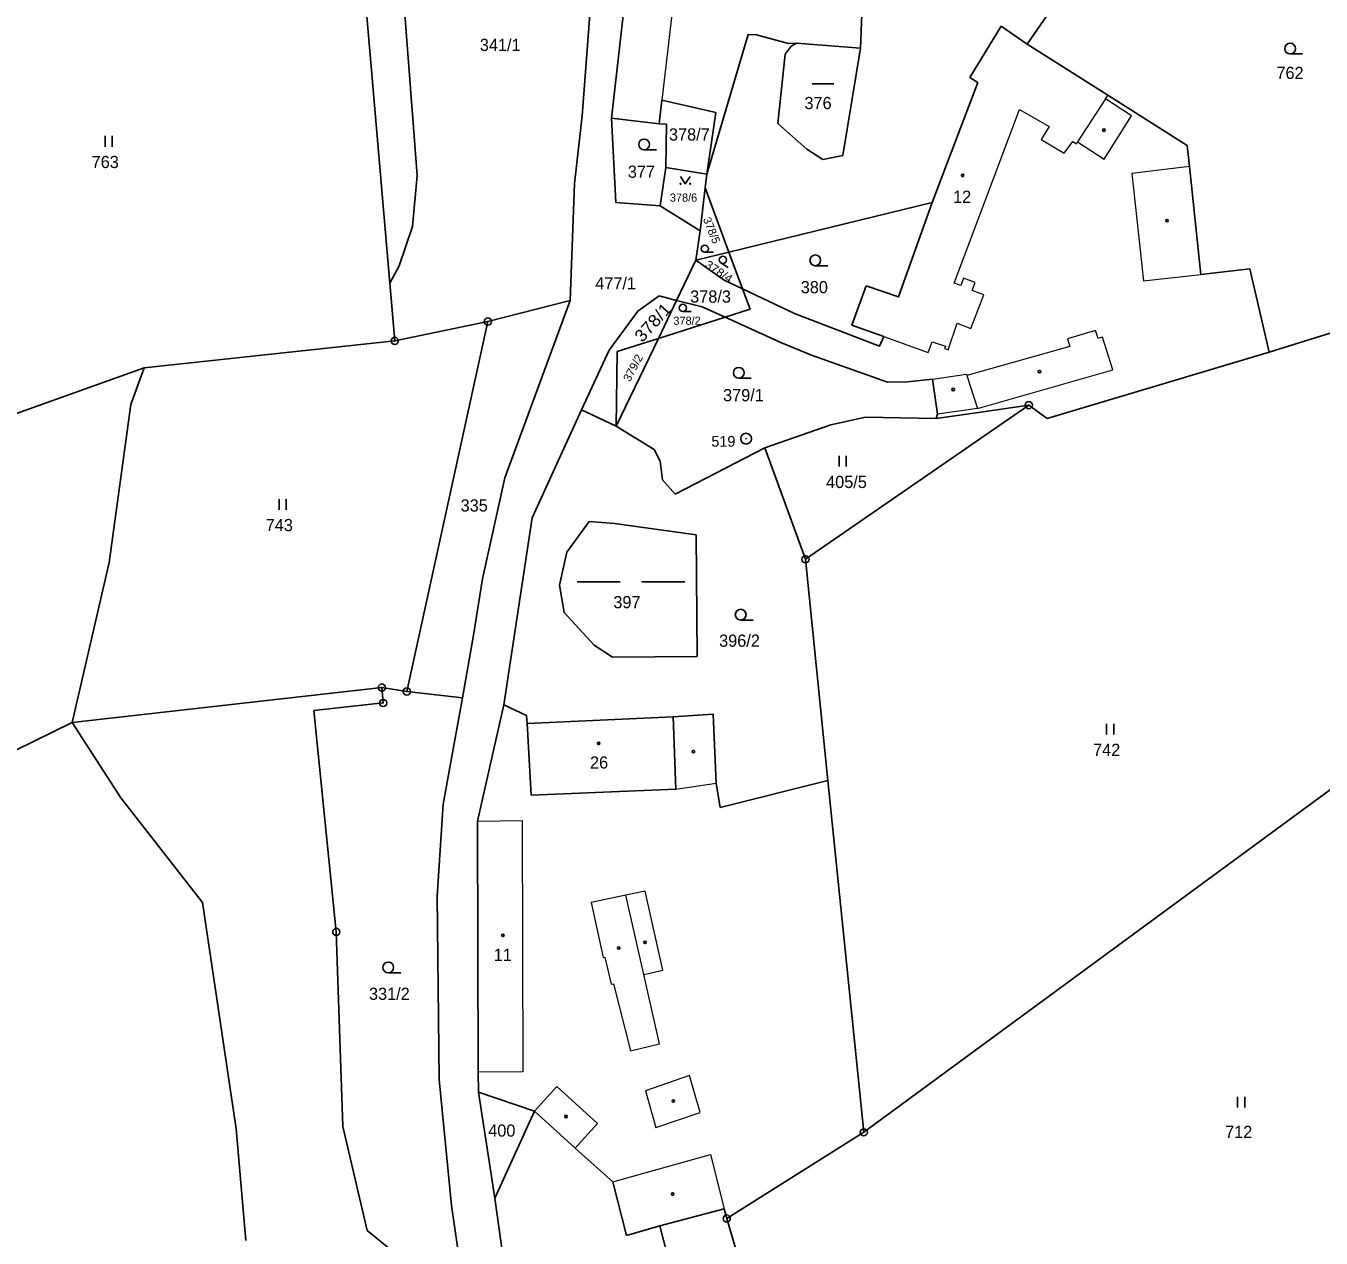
# Model space of a CAD drawing. Extents: x -719614 to -717765, y -1095834 to -1093862.
# Drawn here: x -719079.2 to -718898.5, y -1094490.2 to -1094321.1 of the extents above; entities that cross this region are included whole.
import ezdxf
from ezdxf.enums import TextEntityAlignment as Align

# ---------------------------------------------------------------- set-up
doc = ezdxf.new("R2010")
doc.units = 0
doc.header["$LTSCALE"] = 0.68
for name, color, linetype, lineweight in [('1', 7, 'Continuous', 25), ('3', 7, 'Continuous', 25), ('4', 7, 'Continuous', 13), ('5', 7, 'Continuous', 25), ('8', 7, 'Continuous', 25)]:
    doc.layers.add(name, color=color, linetype=linetype, lineweight=lineweight)
doc.layers.add('2', color=7, linetype='Continuous')

msp = doc.modelspace()

# ---------------------------------------------------------------- linework, layer by layer
at = {"layer": '1'}
for p, q in [((-719028.43, -1094357), (-719034.15, -1094290.08)), ((-718939.5, -1094323.68), (-718916.41, -1094290.11)), ((-719001.6, -1094333.67), (-718998.9, -1094297.81)), ((-719027.06, -1094310.11), (-719024.61, -1094341.99)), ((-718962.42, -1094315.26), (-718962.73, -1094324.2)), ((-718997.49, -1094333.99), (-718995.58, -1094317.16)), ((-718947.49, -1094328.33), (-718943.13, -1094321.16)), ((-718939.5, -1094323.68), (-718943.13, -1094321.16)), ((-718984.19, -1094341.79), (-718978.4, -1094322.33)), ((-718978.4, -1094322.33), (-718977.28, -1094322.38)), ((-718977.28, -1094322.38), (-718972.81, -1094323.56)), ((-718973.27, -1094325.06), (-718974.29, -1094334.71)), ((-718972.43, -1094323.96), (-718973.27, -1094325.06)), ((-718972.81, -1094323.56), (-718971.69, -1094323.53)), ((-718971.69, -1094323.53), (-718972.43, -1094323.96)), ((-718962.73, -1094324.2), (-718971.69, -1094323.53)), ((-718965.2, -1094339.21), (-718962.73, -1094324.2)), ((-718928.25, -1094330.79), (-718939.5, -1094323.68)), ((-718946.35, -1094329), (-718947.49, -1094328.33)), ((-718952.72, -1094345.77), (-718946.35, -1094329)), ((-718990.45, -1094331.45), (-718990.84, -1094334.77)), ((-718982.92, -1094333.21), (-718990.45, -1094331.45)), ((-718917.18, -1094337.81), (-718928.25, -1094330.79)), ((-719002.65, -1094343.11), (-719001.6, -1094333.67)), ((-718990.84, -1094334.77), (-718997.49, -1094333.99)), ((-718997.49, -1094333.99), (-718996.89, -1094345.75)), ((-718984.19, -1094341.79), (-718982.92, -1094333.21)), ((-718989.8, -1094334.8), (-718990.84, -1094334.77)), ((-718989.92, -1094340.85), (-718989.8, -1094334.8)), ((-718974.29, -1094334.71), (-718970.22, -1094338.32)), ((-718970.22, -1094338.32), (-718968.01, -1094339.77)), ((-718968.01, -1094339.77), (-718965.2, -1094339.21)), ((-718916.84, -1094340.74), (-718917.18, -1094337.81)), ((-718990.71, -1094346.23), (-718989.92, -1094340.85)), ((-718984.19, -1094341.79), (-718989.92, -1094340.85)), ((-718915.24, -1094355.77), (-718916.84, -1094340.74)), ((-719024.61, -1094341.99), (-719025.25, -1094349.08)), ((-719003.27, -1094359.42), (-719002.65, -1094343.11)), ((-718984.41, -1094343.72), (-718984.19, -1094341.79)), ((-718985.14, -1094349.71), (-718984.41, -1094343.72)), ((-718981.1, -1094352.68), (-718984.41, -1094343.72)), ((-718996.89, -1094345.75), (-718990.71, -1094346.23)), ((-718990.71, -1094346.23), (-718985.14, -1094349.71)), ((-718952.72, -1094345.77), (-718981.1, -1094352.68)), ((-719025.25, -1094349.08), (-719027.1, -1094354.57)), ((-718985.14, -1094349.71), (-718985.71, -1094353.8)), ((-718988.4, -1094359.4), (-718985.71, -1094353.8)), ((-718981.1, -1094352.68), (-718985.71, -1094353.8)), ((-718985.71, -1094353.8), (-718981.76, -1094356.57)), ((-718979.22, -1094357.77), (-718981.1, -1094352.68)), ((-719027.1, -1094354.57), (-719028.43, -1094357)), ((-718908.4, -1094354.98), (-718915.24, -1094355.77)), ((-718905.73, -1094366.61), (-718908.4, -1094354.98)), ((-719027.74, -1094365.06), (-719028.43, -1094357)), ((-718981.76, -1094356.57), (-718979.22, -1094357.77)), ((-718963.96, -1094362.85), (-718961.97, -1094357.37)), ((-719003.27, -1094359.42), (-719014.74, -1094362.35)), ((-719012.4, -1094384.15), (-719003.27, -1094359.42)), ((-718993.84, -1094360.92), (-718990.85, -1094358.78)), ((-718990.95, -1094364.7), (-718988.4, -1094359.4)), ((-718990.85, -1094358.78), (-718988.4, -1094359.4)), ((-718988.4, -1094359.4), (-718984.85, -1094360.29)), ((-718978.16, -1094360.64), (-718979.22, -1094357.77)), ((-718979.22, -1094357.77), (-718971.95, -1094361.21)), ((-718997.83, -1094366.36), (-718993.84, -1094360.92)), ((-718981.64, -1094361.74), (-718984.85, -1094360.29)), ((-718981.64, -1094361.74), (-718978.16, -1094360.64)), ((-718905.73, -1094366.61), (-718887.07, -1094360.81)), ((-719014.74, -1094362.35), (-719027.74, -1094365.06)), ((-719014.74, -1094362.35), (-719026.05, -1094413.96)), ((-718990.95, -1094364.7), (-718981.64, -1094361.74)), ((-718973.78, -1094365.3), (-718981.64, -1094361.74)), ((-718959.47, -1094364.43), (-718963.96, -1094362.85)), ((-718996.84, -1094376.95), (-718990.95, -1094364.7)), ((-718996.71, -1094366.53), (-718990.95, -1094364.7)), ((-719062.72, -1094368.82), (-719027.74, -1094365.06)), ((-719001.68, -1094374.69), (-718997.83, -1094366.36)), ((-718996.84, -1094376.95), (-718996.71, -1094366.53)), ((-718969.6, -1094367.04), (-718973.78, -1094365.3)), ((-718936.7, -1094375.88), (-718905.73, -1094366.61)), ((-718958.99, -1094370.8), (-718969.6, -1094367.04)), ((-719119.88, -1094389.25), (-719062.72, -1094368.82)), ((-719062.72, -1094368.82), (-719064.56, -1094373.92)), ((-718956.18, -1094370.78), (-718958.99, -1094370.8)), ((-718952.68, -1094370.41), (-718956.18, -1094370.78)), ((-718952.01, -1094375.29), (-718952.68, -1094370.41)), ((-719064.56, -1094373.92), (-719067.61, -1094395.96)), ((-719008.54, -1094389.73), (-719001.68, -1094374.69)), ((-719001.68, -1094374.69), (-718996.84, -1094376.95)), ((-718970.42, -1094395.52), (-718939.26, -1094374.01)), ((-718966.87, -1094376.75), (-718962.06, -1094375.69)), ((-718962.06, -1094375.69), (-718952.19, -1094375.87)), ((-718952.19, -1094375.87), (-718946.3, -1094375.04)), ((-718952.19, -1094375.87), (-718952.01, -1094375.29)), ((-718946.3, -1094375.04), (-718939.26, -1094374.01)), ((-718939.26, -1094374.01), (-718936.7, -1094375.88)), ((-718996.84, -1094376.95), (-718991.53, -1094380.18)), ((-718976.08, -1094379.95), (-718966.87, -1094376.75)), ((-718991.53, -1094380.18), (-718990.72, -1094381.84)), ((-718988.6, -1094386.42), (-718976.08, -1094379.95)), ((-718976.08, -1094379.95), (-718970.42, -1094395.52)), ((-718990.72, -1094381.84), (-718990.37, -1094384.42)), ((-719015.51, -1094398.24), (-719012.4, -1094384.15)), ((-718990.37, -1094384.42), (-718988.6, -1094386.42)), ((-719012.53, -1094415.83), (-719008.54, -1094389.73)), ((-719003.74, -1094394.5), (-719000.63, -1094390.25)), ((-719000.63, -1094390.25), (-718997.06, -1094390.54)), ((-718997.06, -1094390.54), (-718985.66, -1094392.1)), ((-718985.66, -1094392.1), (-718985.53, -1094409.09)), ((-719004.76, -1094399.14), (-719003.74, -1094394.5)), ((-718967.28, -1094426.37), (-718970.42, -1094395.52)), ((-719067.61, -1094395.96), (-719072.77, -1094418.27)), ((-719016.77, -1094406.11), (-719015.51, -1094398.24)), ((-719004.08, -1094402.93), (-719004.76, -1094399.14)), ((-718999.93, -1094407.48), (-719004.08, -1094402.93)), ((-719018.28, -1094414.83), (-719016.77, -1094406.11)), ((-718997.37, -1094409.15), (-718999.93, -1094407.48)), ((-718962.29, -1094475.45), (-718870.17, -1094407.82)), ((-718985.53, -1094409.09), (-718997.37, -1094409.15)), ((-719072.77, -1094418.27), (-719029.53, -1094413.41)), ((-719029.36, -1094415.56), (-719029.53, -1094413.41)), ((-719029.53, -1094413.41), (-719026.05, -1094413.96)), ((-719018.28, -1094414.83), (-719026.05, -1094413.96)), ((-719020.99, -1094429.68), (-719018.28, -1094414.83)), ((-719039.03, -1094416.62), (-719029.36, -1094415.56)), ((-719035.9, -1094447.49), (-719039.03, -1094416.62)), ((-719016.17, -1094432.05), (-719012.53, -1094415.83)), ((-719009.37, -1094417.32), (-719012.53, -1094415.83)), ((-718983.3, -1094417.14), (-718988.89, -1094417.5)), ((-718982.87, -1094426.76), (-718983.3, -1094417.14)), ((-719072.77, -1094418.27), (-719150.62, -1094456.67)), ((-719065.98, -1094428.79), (-719072.77, -1094418.27)), ((-719009.27, -1094418.42), (-719009.37, -1094417.32)), ((-718988.89, -1094417.5), (-719009.27, -1094418.42)), ((-719009.27, -1094418.42), (-719008.68, -1094428.43)), ((-718988.51, -1094427.57), (-718988.89, -1094417.5)), ((-719008.68, -1094428.43), (-718988.51, -1094427.57)), ((-718982.32, -1094430.13), (-718982.87, -1094426.76)), ((-718982.32, -1094430.13), (-718967.28, -1094426.37)), ((-718962.29, -1094475.45), (-718967.28, -1094426.37)), ((-719054.59, -1094443.4), (-719065.98, -1094428.79)), ((-719021.8, -1094442.49), (-719020.99, -1094429.68)), ((-719016.08, -1094467.06), (-719016.17, -1094432.05)), ((-719021.55, -1094468.09), (-719021.8, -1094442.49)), ((-719049.85, -1094474.97), (-719054.59, -1094443.4)), ((-719035, -1094474.65), (-719035.9, -1094447.49)), ((-719016.08, -1094467.06), (-719016.07, -1094469.86)), ((-719019.84, -1094485.67), (-719021.55, -1094468.09)), ((-719016.07, -1094469.86), (-719008.26, -1094472.5)), ((-719013.75, -1094484.64), (-719016.07, -1094469.86)), ((-719013.75, -1094484.64), (-719008.26, -1094472.5)), ((-719002.57, -1094477.64), (-719008.26, -1094472.5)), ((-719048.5, -1094490.56), (-719049.85, -1094474.97)), ((-719031.6, -1094489.15), (-719035, -1094474.65)), ((-718981.41, -1094487.48), (-718962.29, -1094475.45)), ((-718997.31, -1094482.36), (-719002.57, -1094477.64)), ((-718995.38, -1094489.85), (-718997.31, -1094482.36)), ((-719017.63, -1094500.49), (-719019.84, -1094485.67)), ((-719006.69, -1094535.86), (-719013.75, -1094484.64)), ((-718990.77, -1094488.5), (-718981.78, -1094486.13)), ((-718981.78, -1094486.13), (-718981.41, -1094487.48)), ((-718971.55, -1094520.7), (-718981.41, -1094487.48)), ((-719017.63, -1094500.49), (-719031.6, -1094489.15)), ((-718990.77, -1094488.5), (-718995.38, -1094489.85)), ((-718981.69, -1094523.35), (-718990.77, -1094488.5))]:
    msp.add_line(p, q, dxfattribs=at)
for points in [[(-718961.97, -1094357.37), (-718957.43, -1094358.91), (-718952.72, -1094345.77)], [(-718971.95, -1094361.21), (-718960.07, -1094365.78), (-718959.47, -1094364.43)]]:
    msp.add_lwpolyline(points, dxfattribs=at)
at = {"layer": '3'}
for p, q in [((-718902.793, -1094325.03), (-718901.043, -1094325.03)), ((-718969.478, -1094329.21), (-718966.478, -1094329.21)), ((-719068.171, -1094337.96), (-719068.171, -1094336.46)), ((-719067.17, -1094337.96), (-719067.17, -1094336.46)), ((-718992.943, -1094338.4), (-718991.193, -1094338.4)), ((-718984.475, -1094352.69), (-718983.303, -1094352.69)), ((-718982.216, -1094354.163), (-718981.233, -1094354.801)), ((-718969.053, -1094354.57), (-718967.303, -1094354.57)), ((-718987.535, -1094360.95), (-718986.363, -1094360.95)), ((-718979.733, -1094370.25), (-718977.983, -1094370.25)), ((-718965.741, -1094382.57), (-718965.741, -1094381.07)), ((-718964.74, -1094382.57), (-718964.74, -1094381.07)), ((-719043.881, -1094388.61), (-719043.881, -1094387.11)), ((-719042.88, -1094388.61), (-719042.88, -1094387.11)), ((-719002.279, -1094398.64), (-718996.279, -1094398.64)), ((-718993.279, -1094398.64), (-718987.279, -1094398.64)), ((-718979.463, -1094403.99), (-718977.713, -1094403.99)), ((-718928.401, -1094419.96), (-718928.401, -1094418.46)), ((-718927.4, -1094419.96), (-718927.4, -1094418.46)), ((-719028.643, -1094453.2), (-719026.893, -1094453.2)), ((-718910.131, -1094471.98), (-718910.131, -1094470.48)), ((-718909.13, -1094471.98), (-718909.13, -1094470.48))]:
    msp.add_line(p, q, dxfattribs=at)
msp.add_lwpolyline([(-718987.86, -1094342.124), (-718987.19, -1094343.13), (-718986.52, -1094342.124)], dxfattribs=at)
for centre, radius in [((-718902.7929, -1094324.2798), 0.75), ((-718992.9429, -1094337.6498), 0.75), ((-718987.86, -1094343.1296), 0.067), ((-718986.52, -1094343.1296), 0.067), ((-718984.4752, -1094352.1874), 0.5025), ((-718981.9422, -1094353.7411), 0.5025), ((-718969.0529, -1094353.8198), 0.75), ((-718987.5352, -1094360.4474), 0.5025), ((-718979.7329, -1094369.4998), 0.75), ((-718979.4629, -1094403.2398), 0.75), ((-719028.6429, -1094452.4498), 0.75)]:
    msp.add_circle(centre, radius, dxfattribs=at)
at = {"layer": '4'}
for p, q in [((-718988.07, -1094310.99), (-718990.45, -1094331.45)), ((-718928.57, -1094331.28), (-718932.44, -1094337.29)), ((-718928.57, -1094331.28), (-718928.25, -1094330.79)), ((-718924.92, -1094333.67), (-718928.57, -1094331.28)), ((-718949.66, -1094357), (-718940.56, -1094332.77)), ((-718928.73, -1094339.68), (-718924.92, -1094333.67)), ((-718937.54, -1094336.95), (-718934.3, -1094338.86)), ((-718934.3, -1094338.86), (-718933.13, -1094337.22)), ((-718933.13, -1094337.22), (-718932.58, -1094337.55)), ((-718932.58, -1094337.55), (-718932.44, -1094337.29)), ((-718932.44, -1094337.29), (-718928.73, -1094339.68)), ((-718916.84, -1094340.74), (-718924.86, -1094341.69)), ((-718924.86, -1094341.69), (-718923.25, -1094356.66)), ((-718923.25, -1094356.66), (-718915.24, -1094355.77)), ((-718948.75, -1094357.34), (-718949.66, -1094357)), ((-718948.35, -1094356.3), (-718948.75, -1094357.34)), ((-718946.76, -1094356.9), (-718948.35, -1094356.3)), ((-718947.14, -1094358), (-718946.76, -1094356.9)), ((-718947.37, -1094363.32), (-718945.53, -1094358.63)), ((-718945.53, -1094358.63), (-718947.14, -1094358)), ((-718950.51, -1094366.29), (-718949.25, -1094362.59)), ((-718949.25, -1094362.59), (-718947.37, -1094363.32)), ((-718959.47, -1094364.43), (-718953.29, -1094366.66)), ((-718929.95, -1094363.59), (-718933.87, -1094364.77)), ((-718933.87, -1094364.77), (-718933.55, -1094365.82)), ((-718929.6, -1094364.7), (-718929.95, -1094363.59)), ((-718928.96, -1094364.51), (-718929.6, -1094364.7)), ((-718927.54, -1094369.08), (-718928.96, -1094364.51)), ((-718953.29, -1094366.66), (-718952.74, -1094365.2)), ((-718952.74, -1094365.2), (-718950.9, -1094365.79)), ((-718950.9, -1094365.79), (-718951.01, -1094366.13)), ((-718951.01, -1094366.13), (-718950.51, -1094366.29)), ((-718933.55, -1094365.82), (-718947.91, -1094369.86)), ((-718952.68, -1094370.41), (-718947.95, -1094369.69)), ((-718947.95, -1094369.69), (-718947.91, -1094369.86)), ((-718947.91, -1094369.86), (-718946.42, -1094374.5)), ((-718946.42, -1094374.5), (-718927.54, -1094369.08)), ((-718946.42, -1094374.5), (-718952.01, -1094375.29)), ((-718988.51, -1094427.57), (-718982.87, -1094426.76)), ((-719016.17, -1094432.05), (-719009.96, -1094431.97)), ((-719009.96, -1094431.97), (-719009.85, -1094467.03)), ((-718995.48, -1094442.36), (-719000.32, -1094443.39)), ((-718992.81, -1094441.8), (-718995.48, -1094442.36)), ((-718992.97, -1094453.45), (-718995.48, -1094442.36)), ((-718990.31, -1094452.82), (-718992.81, -1094441.8)), ((-719000.32, -1094443.39), (-718998.67, -1094451.06)), ((-718998.67, -1094451.06), (-718998.43, -1094451.01)), ((-718998.43, -1094451.01), (-718997.52, -1094454.8)), ((-718992.97, -1094453.45), (-718990.31, -1094452.82)), ((-718997.52, -1094454.8), (-718997.2, -1094454.73)), ((-718997.2, -1094454.73), (-718994.83, -1094464.09)), ((-718990.78, -1094463.13), (-718992.97, -1094453.45)), ((-718994.83, -1094464.09), (-718990.78, -1094463.13)), ((-719009.85, -1094467.03), (-719016.08, -1094467.06)), ((-718986.6, -1094467.51), (-718992.73, -1094469.65)), ((-718985.13, -1094472.69), (-718986.6, -1094467.51)), ((-719008.26, -1094472.5), (-719005.11, -1094469.06)), ((-719005.11, -1094469.06), (-718999.44, -1094474.21)), ((-718992.73, -1094469.65), (-718991.29, -1094474.8)), ((-718991.29, -1094474.8), (-718985.13, -1094472.69)), ((-718999.44, -1094474.21), (-719002.57, -1094477.64))]:
    msp.add_line(p, q, dxfattribs=at)
for points in [[(-718940.56, -1094332.77), (-718936.43, -1094335.14), (-718937.54, -1094336.95)], [(-718997.31, -1094482.36), (-718983.67, -1094478.56), (-718981.78, -1094486.13)]]:
    msp.add_lwpolyline(points, dxfattribs=at)
at = {"layer": '5'}
for centre in [(-718928.7768, -1094335.6492), (-718948.4768, -1094341.9692), (-718919.9668, -1094348.2892), (-718937.7668, -1094369.3492), (-718949.8168, -1094371.8392), (-718999.2768, -1094421.1992), (-718986.0568, -1094422.3392), (-719012.6468, -1094447.9792), (-718996.4768, -1094449.7292), (-718992.8068, -1094448.9492), (-718988.8568, -1094471.0892), (-719003.8468, -1094473.2392), (-718988.9568, -1094484.0692)]:
    msp.add_circle(centre, 0.175, dxfattribs=at)
at = {"layer": '8'}
for centre, radius in [((-719014.74, -1094362.3499), 0.5), ((-719014.74, -1094362.3499), 0.0303), ((-719027.74, -1094365.0599), 0.5), ((-719027.74, -1094365.0599), 0.0303), ((-718939.26, -1094374.0099), 0.5), ((-718939.26, -1094374.0099), 0.0303), ((-718978.71, -1094378.6898), 0.75), ((-718978.71, -1094378.6898), 0.03), ((-718970.42, -1094395.5199), 0.5), ((-718970.42, -1094395.5199), 0.0303), ((-719029.53, -1094413.4099), 0.5), ((-719029.53, -1094413.4099), 0.0303), ((-719026.05, -1094413.9599), 0.5), ((-719029.36, -1094415.5599), 0.5), ((-719026.05, -1094413.9599), 0.0303), ((-719029.36, -1094415.5599), 0.0303), ((-719035.9, -1094447.4899), 0.5), ((-719035.9, -1094447.4899), 0.0303), ((-718962.29, -1094475.4499), 0.5), ((-718962.29, -1094475.4499), 0.0303), ((-718981.41, -1094487.4799), 0.5), ((-718981.41, -1094487.4799), 0.0303)]:
    msp.add_circle(centre, radius, dxfattribs=at)

# ---------------------------------------------------------------- texts
at = {"layer": '2'}
for s, height, p in [('341/1', 1.7, (-719013.02, -1094324.615)), ('762', 1.7, (-718902.809, -1094328.515)), ('376', 1.7, (-718968.669, -1094332.715)), ('378/7', 1.7, (-718986.63, -1094337.105)), ('763', 1.7, (-719068.139, -1094340.942)), ('377', 1.7, (-718993.319, -1094342.295)), ('378/6', 1.14, (-718987.439, -1094345.635)), ('12', 1.7, (-718948.559, -1094345.795)), ('477/1', 1.7, (-718996.92, -1094357.875)), ('380', 1.7, (-718969.189, -1094358.405)), ('378/3', 1.7, (-718983.67, -1094359.715)), ('378/2', 1.14, (-718986.949, -1094362.805)), ('379/1', 1.7, (-718979.08, -1094373.475)), ('405/5', 1.7, (-718964.7, -1094385.575)), ('335', 1.7, (-719016.649, -1094388.855)), ('743', 1.7, (-719043.849, -1094391.592)), ('397', 1.7, (-718995.339, -1094402.345)), ('396/2', 1.7, (-718979.63, -1094407.715)), ('742', 1.7, (-718928.389, -1094422.942)), ('26', 1.7, (-718999.229, -1094424.705)), ('11', 1.7, (-719012.669, -1094451.545)), ('331/2', 1.7, (-719028.49, -1094456.975)), ('400', 1.7, (-719012.799, -1094476.055)), ('712', 1.7, (-718909.969, -1094476.242))]:
    msp.add_text(s, height=height, dxfattribs=at).set_placement(p, align=Align.CENTER)
msp.add_text('378/5', height=1.14, rotation=292, dxfattribs=at).set_placement((-718984.0397, -1094349.845), align=Align.CENTER)
for s, height, rotation, width, p in [('378/4', 1.14, 326, 1.1, (-718982.8172, -1094355.8448)), ('378/1', 1.7, 48, 1.1, (-718991.1025, -1094363.0448)), ('379/2', 1.14, 62, 1.05, (-718993.9857, -1094369.0776))]:
    msp.add_text(s, height=height, rotation=rotation, dxfattribs=dict(at, width=width)).set_placement(p, align=Align.CENTER)
at = {"layer": '8'}
msp.add_text('519', height=1.5, dxfattribs=at).set_placement((-718980.209, -1094379.807), align=Align.RIGHT)

doc.saveas('drawing.dxf')
